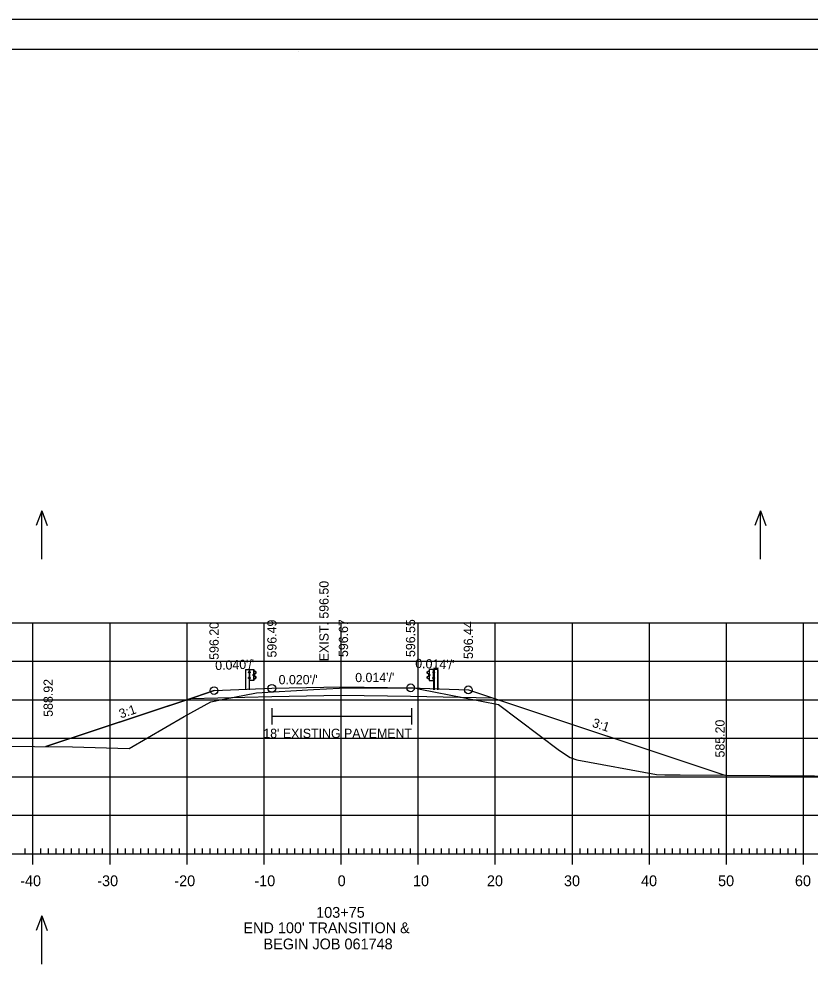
# Model space of a CAD drawing. Extents: x 961436 to 1372525, y 380079 to 2027791.
# Drawn here: x 1371153.1 to 1371255.8, y 380197.8 to 380322.4 of the extents above; entities that cross this region are included whole.
import ezdxf

# ---------------------------------------------------------------- set-up
doc = ezdxf.new("R2010")
doc.units = 0
for name, color, linetype in [('R_Alt Surface', 7, 'Continuous'), ('R_Axis', 7, 'Continuous'), ('R_Axis Annot', 7, 'Continuous'), ('R_Border', 7, 'Continuous'), ('R_Drive', 7, 'Continuous'), ('R_Exist Surface', 7, 'Continuous'), ('R_Fin Surface', 7, 'Continuous'), ('R_Fin Surface Annot', 7, 'Continuous'), ('R_Grid', 7, 'Continuous'), ('R_No Plot', 7, 'Continuous'), ('R_Proposed Road', 7, 'Continuous'), ('R_Water Annot', 7, 'Continuous'), ('R_Xsect Elev', 7, 'Continuous')]:
    doc.layers.add(name, color=color, linetype=linetype)

msp = doc.modelspace()

# ---------------------------------------------------------------- linework, layer by layer
at = {"layer": 'R_Alt Surface'}
for points in [[(1371175.88, 380234.42), (1371156.55, 380227.98)], [(1371175.35, 380234.24), (1371185.88, 380234.47), (1371194.88, 380234.66), (1371203.88, 380234.52), (1371214.5, 380234.31)], [(1371178.38, 380235.25), (1371175.88, 380234.42)], [(1371211.38, 380235.35), (1371213.88, 380234.52)], [(1371213.88, 380234.52), (1371244.66, 380224.26)]]:
    msp.add_lwpolyline(points, dxfattribs=at)
at = {"layer": 'R_Axis'}
for p, q in [((1371153.88, 380214.06), (1371153.88, 380214.76)), ((1371154.88, 380212.66), (1371154.88, 380215.46)), ((1371155.88, 380214.06), (1371155.88, 380214.76)), ((1371156.88, 380214.06), (1371156.88, 380214.76)), ((1371157.88, 380214.06), (1371157.88, 380214.76)), ((1371158.88, 380214.06), (1371158.88, 380214.76)), ((1371159.88, 380214.06), (1371159.88, 380214.76)), ((1371160.88, 380214.06), (1371160.88, 380214.76)), ((1371161.88, 380214.06), (1371161.88, 380214.76)), ((1371162.88, 380214.06), (1371162.88, 380214.76)), ((1371163.88, 380214.06), (1371163.88, 380214.76)), ((1371164.88, 380212.66), (1371164.88, 380215.46)), ((1371165.88, 380214.06), (1371165.88, 380214.76)), ((1371166.88, 380214.06), (1371166.88, 380214.76)), ((1371167.88, 380214.06), (1371167.88, 380214.76)), ((1371168.88, 380214.06), (1371168.88, 380214.76)), ((1371169.88, 380214.06), (1371169.88, 380214.76)), ((1371170.88, 380214.06), (1371170.88, 380214.76)), ((1371171.88, 380214.06), (1371171.88, 380214.76)), ((1371172.88, 380214.06), (1371172.88, 380214.76)), ((1371173.88, 380214.06), (1371173.88, 380214.76)), ((1371174.88, 380212.66), (1371174.88, 380215.46)), ((1371175.88, 380214.06), (1371175.88, 380214.76)), ((1371176.88, 380214.06), (1371176.88, 380214.76)), ((1371177.88, 380214.06), (1371177.88, 380214.76)), ((1371178.88, 380214.06), (1371178.88, 380214.76)), ((1371179.88, 380214.06), (1371179.88, 380214.76)), ((1371180.88, 380214.06), (1371180.88, 380214.76)), ((1371181.88, 380214.06), (1371181.88, 380214.76)), ((1371182.88, 380214.06), (1371182.88, 380214.76)), ((1371183.88, 380214.06), (1371183.88, 380214.76)), ((1371184.88, 380212.66), (1371184.88, 380215.46)), ((1371185.88, 380214.06), (1371185.88, 380214.76)), ((1371186.88, 380214.06), (1371186.88, 380214.76)), ((1371187.88, 380214.06), (1371187.88, 380214.76)), ((1371188.88, 380214.06), (1371188.88, 380214.76)), ((1371189.88, 380214.06), (1371189.88, 380214.76)), ((1371190.88, 380214.06), (1371190.88, 380214.76)), ((1371191.88, 380214.06), (1371191.88, 380214.76)), ((1371192.88, 380214.06), (1371192.88, 380214.76)), ((1371193.88, 380214.06), (1371193.88, 380214.76)), ((1371194.88, 380212.66), (1371194.88, 380215.46)), ((1371195.88, 380214.06), (1371195.88, 380214.76)), ((1371196.88, 380214.06), (1371196.88, 380214.76)), ((1371197.88, 380214.06), (1371197.88, 380214.76)), ((1371198.88, 380214.06), (1371198.88, 380214.76)), ((1371199.88, 380214.06), (1371199.88, 380214.76)), ((1371200.88, 380214.06), (1371200.88, 380214.76)), ((1371201.88, 380214.06), (1371201.88, 380214.76)), ((1371202.88, 380214.06), (1371202.88, 380214.76)), ((1371203.88, 380214.06), (1371203.88, 380214.76)), ((1371204.88, 380212.66), (1371204.88, 380215.46)), ((1371205.88, 380214.06), (1371205.88, 380214.76)), ((1371206.88, 380214.06), (1371206.88, 380214.76)), ((1371207.88, 380214.06), (1371207.88, 380214.76)), ((1371208.88, 380214.06), (1371208.88, 380214.76)), ((1371209.88, 380214.06), (1371209.88, 380214.76)), ((1371210.88, 380214.06), (1371210.88, 380214.76)), ((1371211.88, 380214.06), (1371211.88, 380214.76)), ((1371212.88, 380214.06), (1371212.88, 380214.76)), ((1371213.88, 380214.06), (1371213.88, 380214.76)), ((1371214.88, 380212.66), (1371214.88, 380215.46)), ((1371215.88, 380214.06), (1371215.88, 380214.76)), ((1371216.88, 380214.06), (1371216.88, 380214.76)), ((1371217.88, 380214.06), (1371217.88, 380214.76)), ((1371218.88, 380214.06), (1371218.88, 380214.76)), ((1371219.88, 380214.06), (1371219.88, 380214.76)), ((1371220.88, 380214.06), (1371220.88, 380214.76)), ((1371221.88, 380214.06), (1371221.88, 380214.76)), ((1371222.88, 380214.06), (1371222.88, 380214.76)), ((1371223.88, 380214.06), (1371223.88, 380214.76)), ((1371224.88, 380212.66), (1371224.88, 380215.46)), ((1371225.88, 380214.06), (1371225.88, 380214.76)), ((1371226.88, 380214.06), (1371226.88, 380214.76)), ((1371227.88, 380214.06), (1371227.88, 380214.76)), ((1371228.88, 380214.06), (1371228.88, 380214.76)), ((1371229.88, 380214.06), (1371229.88, 380214.76)), ((1371230.88, 380214.06), (1371230.88, 380214.76)), ((1371231.88, 380214.06), (1371231.88, 380214.76)), ((1371232.88, 380214.06), (1371232.88, 380214.76)), ((1371233.88, 380214.06), (1371233.88, 380214.76)), ((1371234.88, 380212.66), (1371234.88, 380215.46)), ((1371235.88, 380214.06), (1371235.88, 380214.76)), ((1371236.88, 380214.06), (1371236.88, 380214.76)), ((1371237.88, 380214.06), (1371237.88, 380214.76)), ((1371238.88, 380214.06), (1371238.88, 380214.76)), ((1371239.88, 380214.06), (1371239.88, 380214.76)), ((1371240.88, 380214.06), (1371240.88, 380214.76)), ((1371241.88, 380214.06), (1371241.88, 380214.76)), ((1371242.88, 380214.06), (1371242.88, 380214.76)), ((1371243.88, 380214.06), (1371243.88, 380214.76)), ((1371244.88, 380212.66), (1371244.88, 380215.46)), ((1371245.88, 380214.06), (1371245.88, 380214.76)), ((1371246.88, 380214.06), (1371246.88, 380214.76)), ((1371247.88, 380214.06), (1371247.88, 380214.76)), ((1371248.88, 380214.06), (1371248.88, 380214.76)), ((1371249.88, 380214.06), (1371249.88, 380214.76)), ((1371250.88, 380214.06), (1371250.88, 380214.76)), ((1371251.88, 380214.06), (1371251.88, 380214.76)), ((1371252.88, 380214.06), (1371252.88, 380214.76)), ((1371253.88, 380214.06), (1371253.88, 380214.76)), ((1371254.88, 380212.66), (1371254.88, 380215.46)), ((1371054.88, 380214.06), (1371334.88, 380214.06))]:
    msp.add_line(p, q, dxfattribs=at)
at = {"layer": 'R_Border'}
for p, q in [((1371036.88, 380318.52), (1371353.06, 380318.52)), ((1371189.4, 380318.26), (1371189.4, 380318.26)), ((1371189.4, 380318.26), (1371189.4, 380318.26))]:
    msp.add_line(p, q, dxfattribs=at)
at = {"layer": 'R_Drive'}
for p, q in [((1371185.86, 380232.99), (1371185.86, 380230.85)), ((1371185.86, 380231.92), (1371203.99, 380231.92)), ((1371203.99, 380232.99), (1371203.99, 380230.85))]:
    msp.add_line(p, q, dxfattribs=at)
at = {"layer": 'R_Exist Surface'}
msp.add_lwpolyline([(1371135.21, 380228.16), (1371160.02, 380227.95), (1371167.38, 380227.74), (1371174.49, 380231.88), (1371177.96, 380233.78), (1371179.66, 380234.12), (1371183.87, 380234.94), (1371191.28, 380235.39), (1371194.64, 380235.56), (1371201.74, 380235.6), (1371204.36, 380235.62), (1371205.14, 380235.44), (1371210.86, 380234.3), (1371215.28, 380233.43), (1371223.23, 380227.47), (1371224.6, 380226.56), (1371225.44, 380226.27), (1371235.78, 380224.34), (1371236.89, 380224.31), (1371238.85, 380224.31), (1371244.76, 380224.26), (1371279.4, 380224.01)], dxfattribs=at)
at = {"layer": 'R_Fin Surface'}
for points in [[(1371156.55, 380227.98), (1371175.35, 380234.24), (1371175.88, 380234.42), (1371178.38, 380235.25), (1371185.88, 380235.55), (1371194.88, 380235.75), (1371203.88, 380235.61), (1371211.38, 380235.35), (1371213.88, 380234.52), (1371214.5, 380234.31), (1371244.66, 380224.26)], [(1371178.38, 380235.25), (1371185.88, 380235.55), (1371194.88, 380235.75), (1371203.88, 380235.61), (1371211.38, 380235.35)]]:
    msp.add_lwpolyline(points, dxfattribs=at)
at = {"layer": 'R_Grid'}
for p, q in [((1371054.88, 380244.06), (1371334.88, 380244.06)), ((1371154.88, 380214.06), (1371154.88, 380244.06)), ((1371164.88, 380214.06), (1371164.88, 380244.06)), ((1371174.88, 380214.06), (1371174.88, 380244.06)), ((1371184.88, 380214.06), (1371184.88, 380244.06)), ((1371194.88, 380214.06), (1371194.88, 380244.06)), ((1371204.88, 380214.06), (1371204.88, 380244.06)), ((1371214.88, 380214.06), (1371214.88, 380244.06)), ((1371224.88, 380214.06), (1371224.88, 380244.06)), ((1371234.88, 380214.06), (1371234.88, 380244.06)), ((1371244.88, 380214.06), (1371244.88, 380244.06)), ((1371254.88, 380214.06), (1371254.88, 380244.06)), ((1371054.88, 380239.06), (1371334.88, 380239.06)), ((1371054.88, 380234.06), (1371334.88, 380234.06)), ((1371054.88, 380229.06), (1371334.88, 380229.06)), ((1371054.88, 380224.06), (1371334.88, 380224.06)), ((1371054.88, 380219.06), (1371334.88, 380219.06)), ((1371054.88, 380214.06), (1371334.88, 380214.06))]:
    msp.add_line(p, q, dxfattribs=at)
at = {"layer": 'R_No Plot'}
msp.add_line((1371024.48, 380322.41), (1371357.81, 380322.41), dxfattribs=at)
for points in [[(1371024.47, 380322.41), (1371357.81, 380322.41), (1371357.81, 380109.08), (1371024.47, 380109.08)], [(1371270.8, 380318.52), (1371290.42, 380318.52), (1371290.42, 380308.64), (1371306.53, 380308.64), (1371329.73, 380308.64), (1371329.85, 380280.48), (1371353.06, 380280.48), (1371353.06, 380113.06), (1371036.88, 380113.06), (1371036.88, 380318.52)]]:
    msp.add_lwpolyline(points, close=True, dxfattribs=at)
for centre in [(1371178.38, 380235.25), (1371185.88, 380235.55), (1371203.88, 380235.61), (1371211.38, 380235.35)]:
    msp.add_circle(centre, 0.5, dxfattribs=at)
at = {"layer": 'R_Proposed Road'}
for p, q in [((1371182.44, 380238), (1371182.44, 380235.33)), ((1371182.47, 380238), (1371182.47, 380235.33)), ((1371182.92, 380236.95), (1371182.86, 380236.95)), ((1371182.86, 380236.84), (1371182.86, 380236.94)), ((1371182.92, 380236.92), (1371182.86, 380236.92)), ((1371182.93, 380237.68), (1371182.87, 380237.68)), ((1371182.87, 380237.57), (1371182.87, 380237.67)), ((1371182.93, 380237.65), (1371182.87, 380237.65)), ((1371182.93, 380237.58), (1371182.87, 380237.58)), ((1371182.93, 380237.55), (1371182.87, 380237.55)), ((1371182.93, 380237.58), (1371182.88, 380237.58)), ((1371182.92, 380236.82), (1371182.92, 380236.95)), ((1371183, 380238.01), (1371182.93, 380238)), ((1371182.93, 380237.55), (1371182.93, 380237.68)), ((1371182.96, 380235.33), (1371182.96, 380238.01)), ((1371183, 380238.01), (1371182.99, 380238.01)), ((1371183.06, 380237.61), (1371183, 380237.61)), ((1371183.01, 380237.68), (1371183.06, 380237.68)), ((1371183.01, 380237.55), (1371183.06, 380237.55)), ((1371183.06, 380236.95), (1371183.01, 380236.95)), ((1371183.06, 380237.68), (1371183.06, 380237.55)), ((1371183.06, 380236.82), (1371183.06, 380236.95)), ((1371183.46, 380237.23), (1371183.46, 380237.33)), ((1371183.52, 380237.31), (1371183.46, 380237.31)), ((1371183.52, 380237.24), (1371183.46, 380237.24)), ((1371183.52, 380237.21), (1371183.46, 380237.21)), ((1371183.52, 380237.34), (1371183.47, 380237.34)), ((1371183.52, 380237.24), (1371183.47, 380237.24)), ((1371183.52, 380237.21), (1371183.52, 380237.34)), ((1371183.53, 380236.55), (1371183.53, 380238)), ((1371183.68, 380237.78), (1371183.56, 380237.84)), ((1371183.67, 380237.76), (1371183.57, 380237.81)), ((1371183.57, 380237.21), (1371183.57, 380237.35)), ((1371183.6, 380237.21), (1371183.6, 380237.35)), ((1371183.62, 380237.42), (1371183.8, 380237.54)), ((1371183.78, 380237.03), (1371183.62, 380237.13)), ((1371183.63, 380237.4), (1371183.82, 380237.51)), ((1371183.79, 380237.05), (1371183.63, 380237.15)), ((1371183.81, 380237.65), (1371183.67, 380237.76)), ((1371183.67, 380236.78), (1371183.81, 380236.9)), ((1371183.82, 380237.67), (1371183.68, 380237.78)), ((1371206.03, 380237.66), (1371206.17, 380237.77)), ((1371206.22, 380237.4), (1371206.04, 380237.51)), ((1371206.05, 380237.64), (1371206.18, 380237.76)), ((1371206.23, 380237.42), (1371206.05, 380237.53)), ((1371206.18, 380236.78), (1371206.05, 380236.9)), ((1371206.06, 380237.05), (1371206.22, 380237.15)), ((1371206.07, 380237.02), (1371206.24, 380237.13)), ((1371206.17, 380237.77), (1371206.29, 380237.84)), ((1371206.18, 380237.76), (1371206.28, 380237.81)), ((1371206.26, 380237.21), (1371206.25, 380237.35)), ((1371206.28, 380237.21), (1371206.28, 380237.35)), ((1371206.32, 380236.55), (1371206.32, 380237.99)), ((1371206.34, 380237.21), (1371206.34, 380237.34)), ((1371206.34, 380237.34), (1371206.39, 380237.34)), ((1371206.34, 380237.31), (1371206.39, 380237.31)), ((1371206.34, 380237.24), (1371206.38, 380237.24)), ((1371206.34, 380237.24), (1371206.39, 380237.24)), ((1371206.34, 380237.21), (1371206.39, 380237.21)), ((1371206.4, 380237.22), (1371206.4, 380237.32)), ((1371206.85, 380237.67), (1371206.79, 380237.67)), ((1371206.79, 380237.67), (1371206.79, 380237.54)), ((1371206.79, 380237.61), (1371206.85, 380237.61)), ((1371206.85, 380237.54), (1371206.79, 380237.54)), ((1371206.79, 380236.82), (1371206.79, 380236.95)), ((1371206.79, 380236.95), (1371206.85, 380236.95)), ((1371206.85, 380238), (1371206.86, 380238)), ((1371206.85, 380238), (1371206.93, 380238)), ((1371206.89, 380235.33), (1371206.89, 380238)), ((1371206.93, 380237.55), (1371206.93, 380237.68)), ((1371206.93, 380237.68), (1371206.98, 380237.68)), ((1371206.93, 380237.65), (1371206.98, 380237.65)), ((1371206.93, 380237.58), (1371206.97, 380237.58)), ((1371206.93, 380237.58), (1371206.98, 380237.58)), ((1371206.93, 380237.55), (1371206.98, 380237.55)), ((1371206.94, 380236.82), (1371206.94, 380236.95)), ((1371206.94, 380236.95), (1371206.99, 380236.95)), ((1371206.94, 380236.92), (1371206.99, 380236.92)), ((1371206.99, 380237.56), (1371206.99, 380237.66)), ((1371207, 380236.83), (1371207, 380236.93)), ((1371207.38, 380238), (1371207.38, 380235.33)), ((1371207.41, 380238), (1371207.41, 380235.33)), ((1371182.92, 380236.85), (1371182.86, 380236.85)), ((1371182.92, 380236.82), (1371182.86, 380236.82)), ((1371182.92, 380236.85), (1371182.87, 380236.85)), ((1371183, 380236.55), (1371182.96, 380236.55)), ((1371183.06, 380236.89), (1371183, 380236.89)), ((1371183.06, 380236.82), (1371183.01, 380236.82)), ((1371183.56, 380236.73), (1371183.67, 380236.78)), ((1371183.57, 380236.71), (1371183.69, 380236.77)), ((1371183.69, 380236.77), (1371183.82, 380236.88)), ((1371206.16, 380236.76), (1371206.03, 380236.88)), ((1371206.29, 380236.7), (1371206.16, 380236.76)), ((1371206.29, 380236.72), (1371206.18, 380236.78)), ((1371206.79, 380236.88), (1371206.85, 380236.88)), ((1371206.79, 380236.82), (1371206.85, 380236.82)), ((1371206.85, 380236.55), (1371206.89, 380236.55)), ((1371206.94, 380236.85), (1371206.98, 380236.85)), ((1371206.94, 380236.85), (1371206.99, 380236.85)), ((1371206.94, 380236.82), (1371206.99, 380236.82))]:
    msp.add_line(p, q, dxfattribs=at)
for points in [[(1371182.44, 380238), (1371182.93, 380238), (1371182.93, 380235.33)], [(1371207.41, 380238), (1371206.93, 380238), (1371206.93, 380235.33)]]:
    msp.add_lwpolyline(points, dxfattribs=at)
for points in [[(1371182.85, 380236.92), (1371182.85, 380236.85), (1371182.83, 380236.85), (1371182.83, 380236.92)], [(1371182.87, 380237.65), (1371182.87, 380237.59), (1371182.84, 380237.59), (1371182.84, 380237.65)], [(1371182.91, 380236.97), (1371182.91, 380236.8), (1371182.92, 380236.8), (1371182.92, 380236.97)], [(1371182.92, 380237.71), (1371182.92, 380237.53), (1371182.94, 380237.53), (1371182.94, 380237.71)], [(1371183.56, 380238), (1371183.56, 380236.55), (1371183, 380236.55), (1371183, 380238.01)], [(1371183.06, 380237.68), (1371183.06, 380237.55), (1371183, 380237.55), (1371183, 380237.68)], [(1371183.06, 380236.95), (1371183.06, 380236.82), (1371183, 380236.82), (1371183, 380236.95)], [(1371183.46, 380237.31), (1371183.46, 380237.24), (1371183.43, 380237.24), (1371183.43, 380237.31)], [(1371183.51, 380237.36), (1371183.51, 380237.19), (1371183.53, 380237.19), (1371183.53, 380237.36)], [(1371206.3, 380238), (1371206.3, 380236.55), (1371206.85, 380236.55), (1371206.85, 380238)], [(1371206.34, 380237.36), (1371206.34, 380237.18), (1371206.33, 380237.18), (1371206.33, 380237.36)], [(1371206.4, 380237.31), (1371206.4, 380237.24), (1371206.42, 380237.24), (1371206.42, 380237.31)], [(1371206.79, 380237.67), (1371206.79, 380237.54), (1371206.85, 380237.54), (1371206.85, 380237.67)], [(1371206.79, 380236.95), (1371206.79, 380236.82), (1371206.85, 380236.82), (1371206.85, 380236.95)], [(1371206.93, 380237.7), (1371206.93, 380237.52), (1371206.92, 380237.52), (1371206.92, 380237.7)], [(1371206.94, 380236.97), (1371206.94, 380236.79), (1371206.93, 380236.79), (1371206.93, 380236.97)], [(1371206.99, 380237.65), (1371206.99, 380237.58), (1371207.01, 380237.58), (1371207.01, 380237.65)], [(1371207, 380236.92), (1371207, 380236.85), (1371207.03, 380236.85), (1371207.03, 380236.92)]]:
    msp.add_lwpolyline(points, close=True, dxfattribs=at)
for centre, radius, start, end in [((1371182.88, 380236.94), 0.0234, 134.5745, 222.2244), ((1371182.95, 380236.89), 0.0979, 159.7423, 200.2577), ((1371182.89, 380237.67), 0.0234, 134.5745, 222.2244), ((1371182.97, 380237.62), 0.0979, 159.7423, 200.2577), ((1371182.89, 380237.57), 0.0265, 140.9334, 216.6234), ((1371183.48, 380237.33), 0.0234, 134.5745, 222.2244), ((1371183.56, 380237.28), 0.0979, 159.7423, 200.2577), ((1371183.48, 380237.23), 0.0265, 140.9334, 216.6234), ((1371183.66, 380237.34), 0.0918, 118.106, 175.0444), ((1371183.65, 380237.2), 0.0747, 171.7804, 246.8536), ((1371183.59, 380237.27), 0.0481, 282.9554, 86.0697), ((1371183.66, 380237.34), 0.066, 118.106, 175.0444), ((1371183.65, 380237.2), 0.049, 171.7804, 246.8536), ((1371183.73, 380236.95), 0.0907, 325.2184, 59.12), ((1371183.73, 380236.95), 0.116, 325.2184, 59.12), ((1371183.77, 380237.59), 0.0658, 299.2499, 57.9783), ((1371183.77, 380237.59), 0.0909, 299.2499, 57.9783), ((1371206.08, 380237.59), 0.0909, 122.0217, 240.7501), ((1371206.12, 380236.95), 0.116, 120.88, 214.7816), ((1371206.08, 380237.59), 0.0658, 122.0217, 240.7501), ((1371206.12, 380236.95), 0.0907, 120.88, 214.7816), ((1371206.26, 380237.27), 0.0481, 93.9303, 257.0446), ((1371206.19, 380237.34), 0.066, 4.9556, 61.894), ((1371206.19, 380237.34), 0.0918, 4.9556, 61.894), ((1371206.21, 380237.2), 0.049, 293.1464, 8.2196), ((1371206.21, 380237.2), 0.0747, 293.1464, 8.2196), ((1371206.37, 380237.32), 0.0234, 317.7756, 45.4255), ((1371206.3, 380237.27), 0.0979, 339.7423, 20.2577), ((1371206.37, 380237.22), 0.0265, 323.3766, 39.0666), ((1371206.96, 380237.66), 0.0234, 317.7756, 45.4255), ((1371206.89, 380237.61), 0.0979, 339.7423, 20.2577), ((1371206.96, 380237.56), 0.0265, 323.3766, 39.0666), ((1371206.97, 380236.93), 0.0234, 317.7756, 45.4255), ((1371206.9, 380236.88), 0.0979, 339.7423, 20.2577), ((1371182.88, 380236.84), 0.0265, 140.9334, 216.6234), ((1371206.97, 380236.83), 0.0265, 323.3766, 39.0666)]:
    msp.add_arc(centre, radius, start, end, dxfattribs=at)
at = {"layer": 'R_Water Annot'}
for p, q in [((1371156.01, 380258.59), (1371155.31, 380256.67)), ((1371156.01, 380252.31), (1371156.01, 380258.59)), ((1371156.01, 380258.59), (1371156.71, 380256.67)), ((1371249.28, 380258.59), (1371248.58, 380256.67)), ((1371249.28, 380252.31), (1371249.28, 380258.59)), ((1371249.28, 380258.59), (1371249.98, 380256.67)), ((1371156.01, 380206.03), (1371155.31, 380204.1)), ((1371156.01, 380199.74), (1371156.01, 380206.03)), ((1371156.01, 380206.03), (1371156.71, 380204.1))]:
    msp.add_line(p, q, dxfattribs=at)

# ---------------------------------------------------------------- texts
at = {"layer": 'R_Axis Annot'}
for s, p in [('-40', (1371153.22, 380209.86)), ('-30', (1371163.22, 380209.86)), ('-20', (1371173.22, 380209.86)), ('-10', (1371183.61, 380209.86)), ('0', (1371194.42, 380209.86)), ('10', (1371204.19, 380209.86)), ('20', (1371213.79, 380209.86)), ('30', (1371223.79, 380209.86)), ('40', (1371233.79, 380209.86)), ('50', (1371243.79, 380209.86)), ('60', (1371253.76, 380209.86)), ('103+75', (1371191.63, 380205.76)), ("END 100' TRANSITION & ", (1371182.19, 380203.76)), ('BEGIN JOB 061748', (1371184.8, 380201.66))]:
    msp.add_text(s, height=1.4, dxfattribs=at).set_placement(p)
at = {"layer": 'R_Fin Surface Annot'}
for s, rotation, p in [('596.49', 90, (1371186.48, 380239.55)), ('596.67', 90, (1371195.77, 380239.61)), ('596.55', 90, (1371204.48, 380239.61)), ('596.20', 90, (1371178.98, 380239.25)), ('596.44', 90, (1371211.98, 380239.35)), ("0.014'/'", 358.0528, (1371204.47, 380238.19)), ("0.040'/'", 2.2906, (1371178.55, 380237.91)), ("0.020'/'", 0.1719, (1371186.76, 380236.07)), ("0.014'/'", 0.1719, (1371196.7, 380236.35)), ('588.92', 90, (1371157.45, 380231.85)), ('3:1', 18.4349, (1371166.27, 380231.62)), ('3:1', 341.5651, (1371227.35, 380230.58)), ('585.20', 90, (1371244.63, 380226.57))]:
    msp.add_text(s, height=1.2, rotation=rotation, dxfattribs=at).set_placement(p)
msp.add_text("18' EXISTING PAVEMENT", height=1.2, dxfattribs=at).set_placement((1371184.77, 380229.1))
at = {"layer": 'R_Xsect Elev'}
msp.add_text('EXIST. 596.50', height=1.2, rotation=90, dxfattribs=at).set_placement((1371193.24, 380239.06))

doc.saveas('drawing.dxf')
